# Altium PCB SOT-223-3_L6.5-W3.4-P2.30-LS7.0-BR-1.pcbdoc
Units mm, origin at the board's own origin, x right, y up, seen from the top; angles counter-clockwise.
Board outline 21.64 x 19.35 mm, 2 copper layers (Top Layer, Bottom Layer), stack 0 mm thick; 1 components, 0 nets, 4 pads, 0 vias.
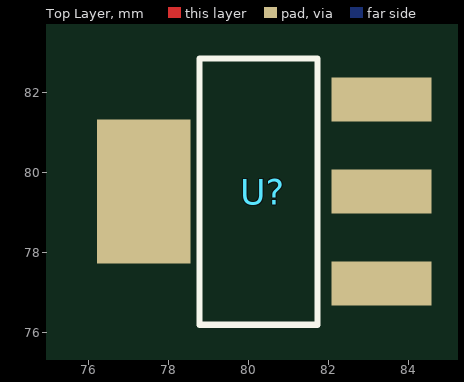
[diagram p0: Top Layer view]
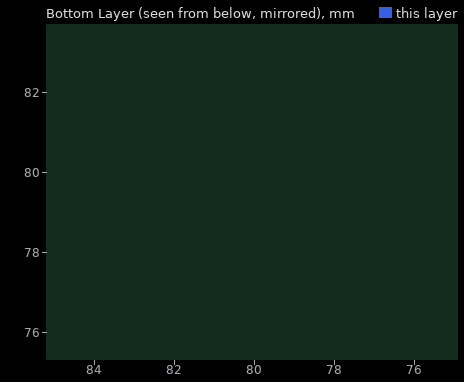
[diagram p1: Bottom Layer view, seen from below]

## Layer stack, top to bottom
Top Layer: signal copper (thickness not stored)
Bottom Layer: signal copper (thickness not stored)

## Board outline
91.492,69.85 69.85,69.85 69.85,89.202 91.492,89.202

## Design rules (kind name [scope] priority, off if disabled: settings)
PasteMaskExpansion "Paste Mask Expansion" [All] p1: expansion=0
SolderMaskExpansion "Solder Mask Expansion" [IsVia] p1: expansion=-25.4 istentingtop=TRUE
SolderMaskExpansion "Solder Mask Expansion" [All] p2: expansion=0.051 istentingtop=FALSE

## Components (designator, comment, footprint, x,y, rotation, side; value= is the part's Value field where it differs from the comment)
U? "" SOT-223-3_L6.5-W3.4-P2.30-LS7.0-BR-1 80.34,79.526 r0 top

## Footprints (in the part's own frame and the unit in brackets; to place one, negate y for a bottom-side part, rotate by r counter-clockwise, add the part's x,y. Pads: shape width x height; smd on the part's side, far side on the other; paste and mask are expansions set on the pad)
SOT-223-3_L6.5-W3.4-P2.30-LS7.0-BR-1 [mm]
  rect 2.5x1.1 smd: 1(2.97,-2.3) 2(2.97,0) 3(2.97,2.3)
  rect 2.34x3.6 smd: 2(-2.97,0)
  silkscreen extent -1.57,-3.33 1.37,3.33

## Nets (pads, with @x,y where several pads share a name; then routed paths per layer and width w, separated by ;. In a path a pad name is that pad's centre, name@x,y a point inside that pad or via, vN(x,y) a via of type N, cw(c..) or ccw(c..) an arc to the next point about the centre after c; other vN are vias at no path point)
pads on no net: U?.1 U?.2 U?.3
